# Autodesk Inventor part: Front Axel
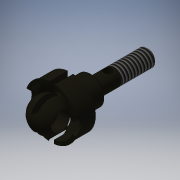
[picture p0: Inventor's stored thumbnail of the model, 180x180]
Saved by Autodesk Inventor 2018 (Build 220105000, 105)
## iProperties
Shininess: 41.0
Compacted: True
Length Units: 11272
Angle Units: 11279
Time Units: 11290
Mass Units: 11286
Length Display Precision: 4
Angle Display Precision: 2
Company: Autodesk
Created: 2000-05
Part Number: Front Axel
Project: Inventor Samples
User Status: IN PROGRESS
Document SubType Name: Modeling
Designer: Autodesk, Inc.
Density: 1.28 g/cm^3
Material: Stiffzel
Mass: 1.36819 g
Surface Area: 14.0023 cm^2
Volume: 1.0689 cm^3
Appearance: Stiffzel
Density: 0.0
Volumn: 0.0
Area: 0.0
PropertySet Name: Model Information
Control State: 0
Master: False
Checked Out: False
Author: Autodesk, Inc.
Revision Number: A
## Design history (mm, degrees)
node "Extrusion1" dims "d1" = 21.844, "d2" = 0
  sketch "Sketch2"
    geometry: C1 r 2.381 at (0, 0)
    constraints: 1 centre point
    dimensions: "d0" = 4.7625 diameter of C1
node "Extrusion2" dims "d4" = 3.81, "d5" = -40 deg
  sketch "Sketch3"
    geometry: C1 r 2.381 at (0, 0) reference; C2 r 3.81 at (0, 0)
    constraints: 1 centre point, 1 coincident
    dimensions: "d3" = 7.62 diameter of C2
node "Chamfer1" dims "d6" = 0.381, "d7" = 0.381, "d42" = 45 deg
workaxis "Work Axis1"
workplane "Work Plane1"
node "Revolution1" dims "d11" = 90 deg
  sketch "Sketch4"
    geometry: L1 (0, 17.323)-(0, -28.372) reference; L2 (-0.613, 3.81)-(0.613, 3.81) reference; L3 (-3.81, 0)-(3.81, 0) reference; L4 (0, 0)-(-7.144, 0); L5 (-7.144, 0)-(-7.144, 5.143); L6 (-7.144, 5.143)-(-7.398, 5.143); L7 (-7.398, 5.143)-(-7.398, 5.397); L8 (-7.398, 5.397)-(-6.331, 5.397); L9 (-6.331, 5.397)-(-6.331, 2.634); L10 (-6.331, 2.634)-(-4.161, 0.813); L11 (-4.161, 0.813)-(0, 0.813); L12 (0, 0)-(0, 0.813); L13 (-3.81, 0)-(-0.613, 3.81) reference; A1 r 4.445 centre (0, 6.35) between (0, 10.795) and (0, 1.905)
    constraints: 18 end point, 4 parallel, 4 perpendicular, 4 point on line, 2 point on circle, 1 centre point, 1 collinear, 1 midpoint
    dimensions: "d9" = 8.89 diameter of A1; "d10" = 2.54 distance from line of L2 A1.centre; "d29" = 14.2875 diameter of L5 L1; "d30" = 0.254 distance between parallel lines of L8 L6; "d31" = 0.254 distance from line of L5 L7.end; "d32" = 0.8128 distance between parallel lines of L3 L11; "d33" = 0.8128 distance between parallel lines of L5 L9; "d34" = 2.54 distance from line of L4.end L10; "d35" = 5.3975 distance between parallel lines of L4 L8
workpoint "Work Point1"
workplane "Work Plane2"
workaxis "Work Axis2"
workplane "Work Plane3"
node "Fillet1" dims "d12" = 0.508
fillet "Fillet2" dims "d41" = 0.8128
sketch "Sketch8"
  geometry: C1 r 2.381 at (0, 0) reference; C2 r 4.001 at (0, 0)
  constraints: 1 centre point, 1 coincident
  dimensions: "d36" = 8.001 diameter of C2
extrude "Extrusion5" join sketch "Sketch8" distance "d37" = 6.35; taper "d38" = 0 deg
chamfer "Chamfer3" distance "d39" = 0.8128; stored, may be unused: second distance "d40" = 0.8128, angle "d43" = 45 deg
node "Revolution2" dims "d14" = 90 deg
  sketch "Sketch5"
    geometry: L1 (5.334, 0)-(-5.334, 0) reference; L2 (-0.794, 14.224)-(0.794, 14.224); L3 (0.794, 14.224)-(0.794, 1.524); L4 (-0.794, 1.524)-(-0.794, 14.224); L5 (0, 17.831)-(0, -7.417) reference; A1 r 0.794 centre (0, 1.524) between (-0.794, 1.524) and (0.794, 1.524)
    constraints: 6 end point, 2 parallel, 2 point on circle, 2 tangent, 1 centre point, 1 perpendicular, 1 point on line
    dimensions: "d13" = 0.79375 radius of A1; "d15" = 12.7 vertical distance of L2.start A1.centre; "d16" = 14.224 distance between parallel lines of L1 L2
node "Mirror1"
node "Extrusion3" dims "d19" = 1.27, "d20" = 0
  sketch "Sketch6"
    geometry: C1 r 2.54 at (0, 6.35); A1 r 4.445 centre (0, 6.35) between (1.406, 10.567) and (-1.406, 10.567) reference
    constraints: 1 centre point, 1 coincident
    dimensions: "d18" = 5.08 diameter of C1
node "Chamfer2" dims "d21" = 0.127, "d22" = 0.127, "d44" = 45 deg
node "Extrusion4" dims "d25" = 25.4, "d26" = 0
  sketch "Sketch7"
    geometry: L1 (0, 4.369)-(0, -26.213) reference; L2 (2, -21.844)-(-2, -21.844) reference; C1 r 1.194 at (0, -10.465)
    constraints: 1 centre point, 1 point on line
    dimensions: "d23" = 11.3792 distance from line of L2 C1.centre; "d24" = 2.3876 diameter of C1
thread "Thread1" dims "d27" = 9.525, "d28" = 0
body "Solid1"
other parameters: "d8" = 90 deg, "d17" = 90 deg
